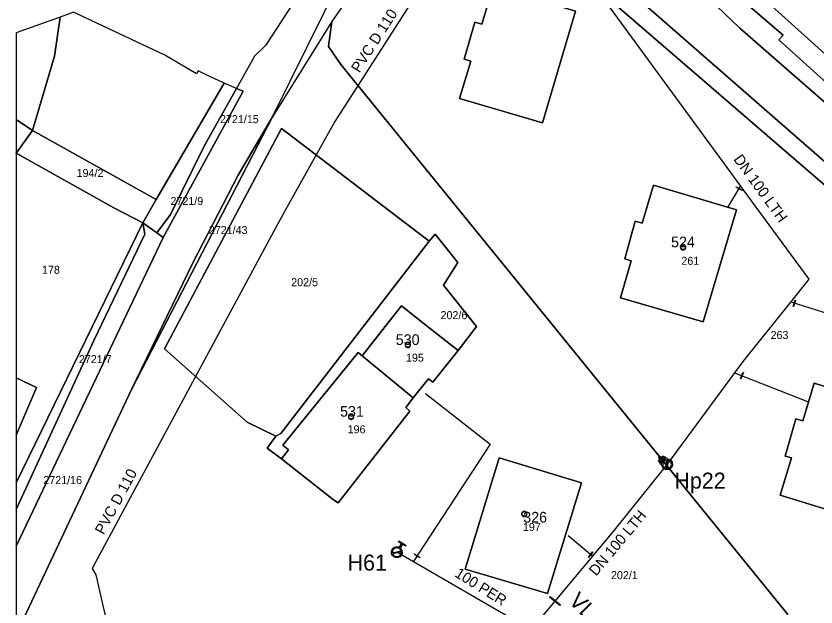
# Model space of a CAD drawing. Extents: x -557590 to -557349, y -1071980 to -1071723.
# Drawn here: x -557590.5 to -557440.5, y -1071889.4 to -1071778.6 of the extents above; entities that cross this region are included whole.
import ezdxf

# ---------------------------------------------------------------- set-up
doc = ezdxf.new("R2010")
doc.units = 0
for name, color, linetype in [('Adresní místo-text', 7, 'Continuous'), ('Armatura - popis', 7, 'Continuous'), ('Armatura vodovodní', 7, 'Continuous'), ('Hydrant', 7, 'Continuous'), ('Označení hydrantu', 7, 'Continuous'), ('Parcela-polygon', 7, 'Continuous'), ('Parcela-text', 7, 'Continuous'), ('Stavební objekt-bod', 7, 'Continuous'), ('Stavební objekt-polygon', 7, 'Continuous'), ('Vodovodní přípojka', 7, 'Continuous'), ('Vodovodní řad', 7, 'Continuous'), ('Řad vodovodní popis', 7, 'Continuous')]:
    doc.layers.add(name, color=color, linetype=linetype)

msp = doc.modelspace()

# ---------------------------------------------------------------- linework, layer by layer
at = {"layer": 'Armatura vodovodní'}
for points in [[(-557455.48, -1071810.64), (-557454.41, -1071811.27), (-557454.45, -1071811.34), (-557455.52, -1071810.7), (-557455.48, -1071810.64)], [(-557444.4, -1071831.89), (-557444.78, -1071833.08), (-557444.85, -1071833.06), (-557444.48, -1071831.86), (-557444.4, -1071831.89)], [(-557454.16, -1071845.46), (-557454.62, -1071846.63), (-557454.69, -1071846.6), (-557454.24, -1071845.43), (-557454.16, -1071845.46)], [(-557515.81, -1071879.44), (-557514.77, -1071880.12), (-557514.81, -1071880.19), (-557515.85, -1071879.5), (-557515.81, -1071879.44)], [(-557482.35, -1071879.11), (-557483.15, -1071880.07), (-557483.21, -1071880.02), (-557482.41, -1071879.06), (-557482.35, -1071879.11)], [(-557490.37, -1071887.39), (-557488.45, -1071888.99), (-557488.55, -1071889.11), (-557490.47, -1071887.51), (-557490.37, -1071887.39)]]:
    msp.add_lwpolyline(points, dxfattribs=at)
at = {"layer": 'Hydrant'}
for points in [[(-557470.05, -1071861.93), (-557469.91, -1071861.79), (-557469.72, -1071861.87)], [(-557469.98, -1071861.31), (-557469.84, -1071861.16)], [(-557469.43, -1071861.95), (-557469.57, -1071862.1), (-557469.8, -1071862.04)], [(-557469.27, -1071861.4), (-557469.36, -1071861.21), (-557469.22, -1071861.07)], [(-557469.25, -1071862), (-557469.12, -1071861.86)], [(-557469.11, -1071861.31), (-557469.04, -1071861.54), (-557469.17, -1071861.68)], [(-557468.73, -1071861.33), (-557468.56, -1071861.44), (-557468.46, -1071861.52)], [(-557468.54, -1071863.43), (-557468.58, -1071861.81)], [(-557468.39, -1071861.81), (-557468.35, -1071863.42)], [(-557469.64, -1071862.58), (-557469.77, -1071862.41)], [(-557469.45, -1071862.78), (-557469.46, -1071862.82)], [(-557518.65, -1071878.22), (-557518.22, -1071877.53), (-557518.8, -1071877.16), (-557518.7, -1071877), (-557517.38, -1071877.83), (-557517.48, -1071877.99), (-557518.06, -1071877.63), (-557518.49, -1071878.32)], [(-557519.91, -1071879.2), (-557518.33, -1071878.84)], [(-557518.29, -1071879.02), (-557519.87, -1071879.39)]]:
    msp.add_lwpolyline(points, dxfattribs=at)
for points, degree in [([(-557469.77, -1071862.41), (-557469.93, -1071862.19), (-557470.05, -1071861.93)], 2), ([(-557469.72, -1071861.87), (-557469.9, -1071861.59), (-557469.98, -1071861.31)], 2), ([(-557469.84, -1071861.16), (-557469.55, -1071861.23), (-557469.27, -1071861.4)], 2), ([(-557469.17, -1071861.68), (-557469.43, -1071861.5), (-557469.73, -1071861.41), (-557469.63, -1071861.71), (-557469.43, -1071861.95)], 3), ([(-557468.35, -1071861.62), (-557468.02, -1071861.66), (-557467.77, -1071861.9), (-557467.47, -1071862.18), (-557467.46, -1071862.6), (-557467.46, -1071863.01), (-557467.74, -1071863.31), (-557468.03, -1071863.61), (-557468.44, -1071863.62), (-557468.85, -1071863.63), (-557469.15, -1071863.34), (-557469.41, -1071863.1), (-557469.45, -1071862.78)], 3), ([(-557468.58, -1071861.81), (-557468.85, -1071861.85), (-557469.06, -1071862.06), (-557469.29, -1071862.3), (-557469.28, -1071862.64), (-557469.27, -1071862.97), (-557469.03, -1071863.21), (-557468.82, -1071863.41), (-557468.54, -1071863.43)], 3), ([(-557469.22, -1071861.07), (-557468.96, -1071861.18), (-557468.73, -1071861.33)], 2), ([(-557469.12, -1071861.86), (-557468.91, -1071861.68), (-557468.64, -1071861.63), (-557468.86, -1071861.45), (-557469.11, -1071861.31)], 3), ([(-557468.46, -1071861.52), (-557468.44, -1071861.54), (-557468.35, -1071861.62)], 2), ([(-557468.35, -1071863.42), (-557468.08, -1071863.39), (-557467.88, -1071863.18), (-557467.65, -1071862.94), (-557467.66, -1071862.6), (-557467.66, -1071862.26), (-557467.91, -1071862.03), (-557468.12, -1071861.83), (-557468.39, -1071861.81)], 3), ([(-557469.8, -1071862.04), (-557469.64, -1071862.28), (-557469.46, -1071862.48)], 2), ([(-557469.46, -1071862.82), (-557469.46, -1071862.8), (-557469.46, -1071862.77), (-557469.57, -1071862.66), (-557469.64, -1071862.58)], 3), ([(-557469.46, -1071862.48), (-557469.43, -1071862.21), (-557469.25, -1071862)], 2), ([(-557518.49, -1071878.32), (-557518.21, -1071878.53), (-557518.13, -1071878.89), (-557518.03, -1071879.29), (-557518.26, -1071879.64), (-557518.47, -1071880), (-557518.88, -1071880.09), (-557519.28, -1071880.18), (-557519.63, -1071879.96), (-557519.98, -1071879.74), (-557520.08, -1071879.34), (-557520.17, -1071878.94), (-557519.95, -1071878.58), (-557519.73, -1071878.23), (-557519.33, -1071878.14), (-557518.97, -1071878.05), (-557518.65, -1071878.22)], 3), ([(-557518.33, -1071878.84), (-557518.43, -1071878.58), (-557518.67, -1071878.42), (-557518.96, -1071878.24), (-557519.29, -1071878.32), (-557519.61, -1071878.39), (-557519.79, -1071878.68), (-557519.95, -1071878.93), (-557519.91, -1071879.2)], 3), ([(-557519.87, -1071879.39), (-557519.78, -1071879.65), (-557519.53, -1071879.8), (-557519.25, -1071879.98), (-557518.92, -1071879.9), (-557518.59, -1071879.83), (-557518.41, -1071879.54), (-557518.26, -1071879.3), (-557518.29, -1071879.02)], 3)]:
    msp.add_open_spline(points, degree=degree, dxfattribs=at)
at = {"layer": 'Parcela-polygon'}
for p, q in [((-557590.46, -1071781.79), (-557590.46, -1071798.04)), ((-557590.46, -1071798.04), (-557590.46, -1071804.35)), ((-557590.46, -1071804.35), (-557590.46, -1071804.36)), ((-557590.46, -1071804.36), (-557590.46, -1071846.45)), ((-557590.46, -1071846.45), (-557590.46, -1071857.16)), ((-557590.46, -1071857.16), (-557590.46, -1071866.09)), ((-557590.46, -1071866.09), (-557590.46, -1071871.1)), ((-557590.46, -1071871.1), (-557590.46, -1071878)), ((-557590.46, -1071878), (-557590.46, -1071894.21))]:
    msp.add_line(p, q, dxfattribs=at)
for points in [[(-557532.39, -1071722.92), (-557523.38, -1071731.14), (-557519.56, -1071737.83), (-557514.49, -1071741.25), (-557511.78, -1071743.08), (-557507.48, -1071745.99), (-557505.88, -1071747.39), (-557407.94, -1071832.97), (-557360.07, -1071868.88), (-557348.7, -1071876.49)], [(-557348.7, -1071872.57), (-557351.33, -1071870.74), (-557377.12, -1071846.76), (-557391.72, -1071835.9), (-557409.36, -1071821.76), (-557431.2, -1071801.51), (-557454.84, -1071780.92), (-557478.14, -1071758.52), (-557494.89, -1071744.04), (-557501.25, -1071740.35), (-557502.97, -1071739.3), (-557506.49, -1071737.04), (-557509.88, -1071734.87), (-557511.32, -1071733.56), (-557512.83, -1071730.19), (-557520.69, -1071722.92)], [(-557491.68, -1071722.92), (-557494.66, -1071727.17), (-557498.21, -1071732.24), (-557371.98, -1071845.92), (-557370.78, -1071844.22), (-557376.44, -1071839.94), (-557374.45, -1071837.16), (-557372.36, -1071834.24), (-557370.27, -1071831.33), (-557368.18, -1071828.42), (-557366.09, -1071825.51), (-557364, -1071822.6), (-557363.05, -1071822.01), (-557359.61, -1071817.07), (-557353.89, -1071820.86), (-557357.44, -1071826.15), (-557355.59, -1071827.4), (-557349.46, -1071818.81), (-557404.92, -1071742.72), (-557414.14, -1071731.67), (-557420.72, -1071725.86), (-557424.8, -1071722.92)], [(-557348.7, -1071864.9), (-557356.49, -1071859.88), (-557361.34, -1071855.51), (-557371.98, -1071845.92), (-557498.21, -1071732.24), (-557498.56, -1071732.08), (-557498.84, -1071732.98), (-557501.22, -1071736.7), (-557499.68, -1071737.96), (-557465.81, -1071765.76), (-557446.72, -1071782.19), (-557447.53, -1071783.1), (-557428.12, -1071800.58), (-557389.66, -1071832.85), (-557377.15, -1071844.11), (-557348.7, -1071869.27)], [(-557348.7, -1071869.27), (-557377.15, -1071844.11), (-557389.66, -1071832.85), (-557428.12, -1071800.58), (-557447.53, -1071783.1), (-557446.72, -1071782.19), (-557465.81, -1071765.76), (-557499.68, -1071737.96), (-557501.22, -1071736.7), (-557503.91, -1071734.49), (-557506.49, -1071737.04), (-557502.97, -1071739.3), (-557501.25, -1071740.35), (-557494.89, -1071744.04), (-557478.14, -1071758.52), (-557454.84, -1071780.92), (-557431.2, -1071801.51), (-557409.36, -1071821.76), (-557391.72, -1071835.9), (-557377.12, -1071846.76), (-557351.33, -1071870.74), (-557348.7, -1071872.57)], [(-557590.46, -1071894.21), (-557589.01, -1071891.45), (-557568.8, -1071848.59), (-557557.24, -1071824.77), (-557548.84, -1071808.44), (-557542.42, -1071797.49), (-557529.5, -1071771.47), (-557511.78, -1071743.08), (-557514.49, -1071741.25), (-557521.38, -1071750.42), (-557524.29, -1071754.35), (-557543.7, -1071784.14), (-557545.78, -1071786.13), (-557549.16, -1071792.19), (-557547.9, -1071792.73), (-557562.91, -1071820.1), (-557590.46, -1071878)], [(-557348.7, -1071876.49), (-557360.07, -1071868.88), (-557407.94, -1071832.97), (-557505.88, -1071747.39), (-557507.48, -1071745.99), (-557509.91, -1071749.02), (-557508.17, -1071750.52), (-557408.88, -1071836.21), (-557387.5, -1071856.25), (-557385.01, -1071858.11), (-557382.34, -1071860.11), (-557379.67, -1071862.11), (-557376.99, -1071864.11), (-557374.36, -1071866.09), (-557371.65, -1071868.11), (-557368.98, -1071870.11), (-557366.31, -1071872.11), (-557363.63, -1071874.12), (-557360.97, -1071876.11), (-557358.29, -1071878.11), (-557356.55, -1071879.44), (-557348.7, -1071885.41)], [(-557408.88, -1071836.21), (-557508.17, -1071750.52), (-557509.91, -1071749.02), (-557531.29, -1071779.68), (-557531.92, -1071784.31), (-557529.61, -1071787.72), (-557445.83, -1071890.76)], [(-557590.46, -1071798.04), (-557587.38, -1071800.05), (-557583.28, -1071786.13), (-557582.18, -1071778.84), (-557590.46, -1071781.79)], [(-557445.83, -1071890.76), (-557529.61, -1071787.72), (-557531.92, -1071784.31), (-557531.29, -1071779.68), (-557542.42, -1071797.49), (-557568.8, -1071848.59), (-557589.01, -1071891.45)], [(-557590.46, -1071804.35), (-557590.46, -1071804.35), (-557587.38, -1071800.05), (-557590.46, -1071798.04)], [(-557513.02, -1071820.8), (-557511.94, -1071819.53), (-557507.66, -1071824.81), (-557510.33, -1071829.09), (-557504.14, -1071836.78), (-557507.6, -1071841.29), (-557512.38, -1071847.24), (-557513.19, -1071846.59), (-557515.28, -1071849.25), (-557516.01, -1071850.19), (-557517.41, -1071851.98), (-557516.66, -1071852.7), (-557530.08, -1071869.85), (-557530.96, -1071869.3), (-557540.72, -1071861.63), (-557543.37, -1071859.63), (-557541.76, -1071857.33), (-557547.13, -1071854.74), (-557562.62, -1071841.01), (-557540.68, -1071799.68), (-557513.02, -1071820.8)], [(-557590.46, -1071866.09), (-557566.69, -1071817.37), (-557572.16, -1071814.55), (-557590.46, -1071804.35), (-557590.46, -1071804.36)], [(-557590.46, -1071804.36), (-557590.46, -1071804.35), (-557590.46, -1071804.35)], [(-557590.46, -1071871.1), (-557575.79, -1071839.29), (-557566.34, -1071819.48), (-557566.69, -1071817.37), (-557590.46, -1071866.09)], [(-557590.46, -1071878), (-557562.91, -1071820.1), (-557564.05, -1071819.28), (-557566.69, -1071817.37), (-557566.34, -1071819.48), (-557575.79, -1071839.29), (-557590.46, -1071871.1)], [(-557590.46, -1071857.16), (-557587.87, -1071851.19), (-557586.6, -1071848.25), (-557590.46, -1071846.45)], [(-557590.46, -1071846.45), (-557586.6, -1071848.25), (-557587.87, -1071851.19), (-557590.46, -1071857.16)], [(-557431.85, -1071873.19), (-557447.24, -1071868.43), (-557445.12, -1071861.45), (-557446.3, -1071861.09), (-557444.31, -1071854.11), (-557443.01, -1071854.5), (-557440.87, -1071847.45), (-557430.15, -1071850.71)], [(-557484.5, -1071866.11), (-557490.88, -1071886.85), (-557506.29, -1071882.29), (-557499.92, -1071861.43), (-557484.5, -1071866.11)]]:
    msp.add_lwpolyline(points, dxfattribs=at)
for points in [[(-557491.82, -1071798.65), (-557507.35, -1071794.09), (-557505.25, -1071787.08), (-557506.51, -1071786.71), (-557504.5, -1071779.75), (-557503.17, -1071780.15), (-557501.03, -1071773.01), (-557485.62, -1071777.72)], [(-557501.03, -1071773.01), (-557503.17, -1071780.15), (-557504.5, -1071779.75), (-557506.51, -1071786.71), (-557505.25, -1071787.08), (-557507.35, -1071794.09), (-557491.82, -1071798.65), (-557485.62, -1071777.72)], [(-557551.46, -1071791.21), (-557555.08, -1071789.5), (-557556.32, -1071788.92), (-557556.65, -1071789.47), (-557562.59, -1071785.96), (-557579.67, -1071777.91), (-557582.18, -1071778.84), (-557583.28, -1071786.13), (-557587.38, -1071800.05), (-557564.18, -1071813.04)], [(-557549.16, -1071792.19), (-557551.46, -1071791.21), (-557564.18, -1071813.04), (-557566.69, -1071817.37), (-557564.05, -1071819.28), (-557561.52, -1071815.85), (-557555.11, -1071802.86)], [(-557562.91, -1071820.1), (-557547.9, -1071792.73), (-557549.16, -1071792.19), (-557555.11, -1071802.86), (-557561.52, -1071815.85), (-557564.05, -1071819.28)], [(-557568.8, -1071848.59), (-557542.42, -1071797.49), (-557548.84, -1071808.44), (-557557.24, -1071824.77)], [(-557590.46, -1071804.35), (-557572.16, -1071814.55), (-557566.69, -1071817.37), (-557564.18, -1071813.04), (-557587.38, -1071800.05)], [(-557513.02, -1071820.8), (-557540.68, -1071799.68), (-557562.62, -1071841.01), (-557547.13, -1071854.74), (-557541.76, -1071857.33), (-557540.82, -1071856.86)], [(-557474.43, -1071817.09), (-557476.38, -1071824.15), (-557475.17, -1071824.5), (-557477.18, -1071831.41), (-557461.72, -1071835.91), (-557455.47, -1071814.94), (-557471.03, -1071810.33), (-557473.12, -1071817.47)], [(-557475.17, -1071824.5), (-557476.38, -1071824.15), (-557474.43, -1071817.09), (-557473.12, -1071817.47), (-557471.03, -1071810.33), (-557455.47, -1071814.94), (-557461.72, -1071835.91), (-557477.18, -1071831.41)], [(-557511.94, -1071819.53), (-557513.02, -1071820.8), (-557540.82, -1071856.86), (-557541.76, -1071857.33), (-557543.37, -1071859.63), (-557540.72, -1071861.63), (-557539.37, -1071859.91), (-557540.45, -1071859.06), (-557526.36, -1071841.71), (-557525.57, -1071842.32), (-557520.58, -1071835.96), (-557518.23, -1071832.96), (-557513.35, -1071836.79), (-557508.5, -1071840.59), (-557507.6, -1071841.29), (-557504.14, -1071836.78), (-557510.33, -1071829.09), (-557507.66, -1071824.81)], [(-557520.58, -1071835.96), (-557525.57, -1071842.32), (-557516.01, -1071850.19), (-557515.28, -1071849.25), (-557513.19, -1071846.59), (-557512.38, -1071847.24), (-557507.6, -1071841.29), (-557508.5, -1071840.59), (-557513.35, -1071836.79), (-557518.23, -1071832.96)], [(-557525.57, -1071842.32), (-557526.36, -1071841.71), (-557540.45, -1071859.06), (-557539.37, -1071859.91), (-557540.72, -1071861.63), (-557530.96, -1071869.3), (-557530.08, -1071869.85), (-557516.66, -1071852.7), (-557517.41, -1071851.98), (-557516.01, -1071850.19)], [(-557425.5, -1071852.13), (-557430.15, -1071850.71), (-557440.87, -1071847.45), (-557443.01, -1071854.5), (-557444.31, -1071854.11), (-557446.3, -1071861.09), (-557445.12, -1071861.45), (-557447.24, -1071868.43), (-557431.85, -1071873.19)], [(-557499.92, -1071861.43), (-557506.29, -1071882.29), (-557490.88, -1071886.85), (-557484.5, -1071866.11)]]:
    msp.add_lwpolyline(points, close=True, dxfattribs=at)
at = {"layer": 'Stavební objekt-bod'}
for points in [[(-557465.45, -1071821.47), (-557465.32, -1071821.47), (-557465.2, -1071821.53), (-557465.09, -1071821.6), (-557465.02, -1071821.72), (-557464.95, -1071821.84), (-557464.95, -1071821.97), (-557464.95, -1071822.1), (-557465.02, -1071822.22), (-557465.08, -1071822.34), (-557465.2, -1071822.4), (-557465.32, -1071822.47), (-557465.45, -1071822.47), (-557465.58, -1071822.47), (-557465.7, -1071822.4), (-557465.82, -1071822.34), (-557465.88, -1071822.22), (-557465.95, -1071822.1), (-557465.95, -1071821.97), (-557465.95, -1071821.84), (-557465.88, -1071821.72), (-557465.82, -1071821.6), (-557465.7, -1071821.53), (-557465.58, -1071821.47), (-557465.45, -1071821.47)], [(-557465.89, -1071821.97), (-557465.89, -1071822.08), (-557465.83, -1071822.19), (-557465.77, -1071822.29), (-557465.67, -1071822.35), (-557465.56, -1071822.41), (-557465.45, -1071822.41), (-557465.34, -1071822.41), (-557465.23, -1071822.35), (-557465.13, -1071822.29), (-557465.07, -1071822.19), (-557465.01, -1071822.08), (-557465.01, -1071821.97), (-557465.01, -1071821.86), (-557465.07, -1071821.75), (-557465.13, -1071821.65), (-557465.24, -1071821.59), (-557465.34, -1071821.53), (-557465.45, -1071821.53), (-557465.56, -1071821.53), (-557465.67, -1071821.59), (-557465.77, -1071821.65), (-557465.83, -1071821.75), (-557465.89, -1071821.86), (-557465.89, -1071821.97)], [(-557517.04, -1071839.77), (-557516.91, -1071839.77), (-557516.79, -1071839.83), (-557516.68, -1071839.9), (-557516.61, -1071840.02), (-557516.54, -1071840.14), (-557516.54, -1071840.27), (-557516.54, -1071840.4), (-557516.61, -1071840.52), (-557516.67, -1071840.64), (-557516.79, -1071840.7), (-557516.91, -1071840.77), (-557517.04, -1071840.77), (-557517.17, -1071840.77), (-557517.29, -1071840.7), (-557517.41, -1071840.64), (-557517.47, -1071840.52), (-557517.54, -1071840.4), (-557517.54, -1071840.27), (-557517.54, -1071840.14), (-557517.47, -1071840.02), (-557517.41, -1071839.9), (-557517.29, -1071839.83), (-557517.17, -1071839.77), (-557517.04, -1071839.77)], [(-557517.48, -1071840.27), (-557517.48, -1071840.38), (-557517.42, -1071840.49), (-557517.36, -1071840.59), (-557517.26, -1071840.65), (-557517.15, -1071840.71), (-557517.04, -1071840.71), (-557516.93, -1071840.71), (-557516.82, -1071840.65), (-557516.72, -1071840.59), (-557516.66, -1071840.49), (-557516.6, -1071840.38), (-557516.6, -1071840.27), (-557516.6, -1071840.16), (-557516.66, -1071840.05), (-557516.72, -1071839.95), (-557516.83, -1071839.89), (-557516.93, -1071839.83), (-557517.04, -1071839.83), (-557517.15, -1071839.83), (-557517.26, -1071839.89), (-557517.36, -1071839.95), (-557517.42, -1071840.05), (-557517.48, -1071840.16), (-557517.48, -1071840.27)], [(-557527.67, -1071853.21), (-557527.54, -1071853.21), (-557527.42, -1071853.27), (-557527.31, -1071853.34), (-557527.24, -1071853.46), (-557527.17, -1071853.58), (-557527.17, -1071853.71), (-557527.17, -1071853.84), (-557527.24, -1071853.96), (-557527.3, -1071854.08), (-557527.42, -1071854.14), (-557527.54, -1071854.21), (-557527.67, -1071854.21), (-557527.8, -1071854.21), (-557527.92, -1071854.14), (-557528.04, -1071854.08), (-557528.1, -1071853.96), (-557528.17, -1071853.84), (-557528.17, -1071853.71), (-557528.17, -1071853.58), (-557528.1, -1071853.46), (-557528.04, -1071853.34), (-557527.92, -1071853.27), (-557527.8, -1071853.21), (-557527.67, -1071853.21)], [(-557528.11, -1071853.71), (-557528.11, -1071853.82), (-557528.05, -1071853.93), (-557527.99, -1071854.03), (-557527.89, -1071854.09), (-557527.78, -1071854.15), (-557527.67, -1071854.15), (-557527.56, -1071854.15), (-557527.45, -1071854.09), (-557527.35, -1071854.03), (-557527.29, -1071853.93), (-557527.23, -1071853.82), (-557527.23, -1071853.71), (-557527.23, -1071853.6), (-557527.29, -1071853.49), (-557527.35, -1071853.39), (-557527.46, -1071853.33), (-557527.56, -1071853.27), (-557527.67, -1071853.27), (-557527.78, -1071853.27), (-557527.89, -1071853.33), (-557527.99, -1071853.39), (-557528.05, -1071853.49), (-557528.11, -1071853.6), (-557528.11, -1071853.71)], [(-557495.21, -1071871.44), (-557495.08, -1071871.44), (-557494.96, -1071871.5), (-557494.85, -1071871.57), (-557494.78, -1071871.69), (-557494.71, -1071871.81), (-557494.71, -1071871.94), (-557494.71, -1071872.07), (-557494.78, -1071872.19), (-557494.84, -1071872.31), (-557494.96, -1071872.37), (-557495.08, -1071872.44), (-557495.21, -1071872.44), (-557495.34, -1071872.44), (-557495.46, -1071872.37), (-557495.58, -1071872.31), (-557495.64, -1071872.19), (-557495.71, -1071872.07), (-557495.71, -1071871.94), (-557495.71, -1071871.81), (-557495.64, -1071871.69), (-557495.58, -1071871.57), (-557495.46, -1071871.5), (-557495.34, -1071871.44), (-557495.21, -1071871.44)], [(-557495.65, -1071871.94), (-557495.65, -1071872.05), (-557495.59, -1071872.16), (-557495.53, -1071872.26), (-557495.43, -1071872.32), (-557495.32, -1071872.38), (-557495.21, -1071872.38), (-557495.1, -1071872.38), (-557494.99, -1071872.32), (-557494.89, -1071872.26), (-557494.83, -1071872.16), (-557494.77, -1071872.05), (-557494.77, -1071871.94), (-557494.77, -1071871.83), (-557494.83, -1071871.72), (-557494.89, -1071871.62), (-557495, -1071871.56), (-557495.1, -1071871.5), (-557495.21, -1071871.5), (-557495.32, -1071871.5), (-557495.43, -1071871.56), (-557495.53, -1071871.62), (-557495.59, -1071871.72), (-557495.65, -1071871.83), (-557495.65, -1071871.94)]]:
    msp.add_open_spline(points, degree=3, dxfattribs=at)
at = {"layer": 'Stavební objekt-polygon'}
msp.add_line((-557590.46, -1071846.45), (-557590.46, -1071857.16), dxfattribs=at)
for points in [[(-557501.03, -1071773.01), (-557503.17, -1071780.15), (-557504.5, -1071779.75), (-557506.51, -1071786.71), (-557505.25, -1071787.08), (-557507.35, -1071794.09), (-557491.82, -1071798.65), (-557485.62, -1071777.72)], [(-557455.47, -1071814.94), (-557471.03, -1071810.33), (-557473.12, -1071817.47), (-557474.43, -1071817.09), (-557476.38, -1071824.15), (-557475.17, -1071824.5), (-557477.18, -1071831.41), (-557461.72, -1071835.91)], [(-557520.58, -1071835.96), (-557525.57, -1071842.32), (-557516.01, -1071850.19), (-557515.28, -1071849.25), (-557513.19, -1071846.59), (-557512.38, -1071847.24), (-557507.6, -1071841.29), (-557508.5, -1071840.59), (-557513.35, -1071836.79), (-557518.23, -1071832.96)], [(-557516.66, -1071852.7), (-557517.41, -1071851.98), (-557516.01, -1071850.19), (-557525.57, -1071842.32), (-557526.36, -1071841.71), (-557540.45, -1071859.06), (-557539.37, -1071859.91), (-557540.72, -1071861.63), (-557530.96, -1071869.3), (-557530.08, -1071869.85)], [(-557425.5, -1071852.13), (-557430.15, -1071850.71), (-557440.87, -1071847.45), (-557443.01, -1071854.5), (-557444.31, -1071854.11), (-557446.3, -1071861.09), (-557445.12, -1071861.45), (-557447.24, -1071868.43), (-557431.85, -1071873.19)], [(-557506.29, -1071882.29), (-557490.88, -1071886.85), (-557484.5, -1071866.11), (-557499.92, -1071861.43)]]:
    msp.add_lwpolyline(points, close=True, dxfattribs=at)
msp.add_lwpolyline([(-557590.46, -1071857.16), (-557587.87, -1071851.19), (-557586.6, -1071848.25), (-557590.46, -1071846.45)], dxfattribs=at)
at = {"layer": 'Vodovodní přípojka'}
for p, q in [((-557457.04, -1071814.48), (-557454.7, -1071810.54)), ((-557455.82, -1071845.49), (-557442.15, -1071850.84)), ((-557482.44, -1071879.86), (-557487, -1071876.04))]:
    msp.add_line(p, q, dxfattribs=at)
for points in [[(-557426.24, -1071838.24), (-557445.22, -1071832.28), (-557445.33, -1071832.25)], [(-557513.75, -1071849.38), (-557501.63, -1071858.87), (-557516.02, -1071880.9)]]:
    msp.add_lwpolyline(points, dxfattribs=at)
at = {"layer": 'Vodovodní řad'}
msp.add_line((-557541.72, -1071818.13), (-557575.7, -1071881.23), dxfattribs=at)
for points in [[(-557496.75, -1071758.67), (-557512.36, -1071769.71), (-557530.72, -1071798.39), (-557538.44, -1071812.23)], [(-557496.34, -1071759.05), (-557483.57, -1071771.03), (-557454.7, -1071810.54), (-557454.27, -1071811.12), (-557441.87, -1071827.93), (-557445.33, -1071832.25), (-557454.27, -1071843.38), (-557455.82, -1071845.49), (-557468.46, -1071862.62)], [(-557538.44, -1071812.23), (-557538.47, -1071812.28), (-557539.31, -1071813.84), (-557541.71, -1071818.11), (-557541.72, -1071818.13)], [(-557468.47, -1071862.62), (-557478.61, -1071875.28), (-557489.46, -1071888.25)], [(-557489.46, -1071888.25), (-557490.76, -1071889.8), (-557493.98, -1071893.66), (-557519.1, -1071879.11)], [(-557575.7, -1071881.23), (-557576.18, -1071882.13), (-557575.53, -1071883.32)], [(-557575.53, -1071883.32), (-557570.55, -1071904.9), (-557575.62, -1071911.53), (-557578.43, -1071915.2), (-557589.25, -1071929.32), (-557590.46, -1071931.04)]]:
    msp.add_lwpolyline(points, dxfattribs=at)

# ---------------------------------------------------------------- texts
at = {"layer": 'Adresní místo-text'}
for s, p in [('524', (-557467.71, -1071821.97)), ('530', (-557519.3, -1071840.27)), ('531', (-557529.74, -1071853.71)), ('326', (-557495.41, -1071873.55))]:
    msp.add_text(s, height=2, dxfattribs=at).set_placement(p)
at = {"layer": 'Armatura - popis'}
msp.add_text('VL-52', height=3, rotation=315, dxfattribs=at).set_placement((-557487.03, -1071888.45))
at = {"layer": 'Označení hydrantu'}
for s, p in [('Hp22', (-557467.08, -1071867.19)), ('H61', (-557528.32, -1071882.55))]:
    msp.add_text(s, height=3, dxfattribs=at).set_placement(p)
at = {"layer": 'Parcela-text'}
for s, p in [('2721/15', (-557552.23, -1071798.7)), ('194/2', (-557579.1, -1071808.8)), ('2721/9', (-557561.51, -1071814.04)), ('2721/43', (-557554.33, -1071819.49)), ('261', (-557465.78, -1071825.25)), ('178', (-557585.59, -1071826.93)), ('202/5', (-557538.89, -1071829.26)), ('202/6', (-557510.9, -1071835.43)), ('263', (-557449.06, -1071839.15)), ('2721/7', (-557578.68, -1071843.68)), ('195', (-557517.38, -1071843.4)), ('196', (-557528.32, -1071856.83)), ('2721/16', (-557585.34, -1071866.34)), ('197', (-557495.47, -1071875.12)), ('202/1', (-557478.97, -1071884.15))]:
    msp.add_text(s, height=1.5, dxfattribs=at).set_placement(p)
at = {"layer": 'Řad vodovodní popis'}
for s, rotation, p in [('PVC D 110', 57.3745, (-557526.11, -1071789.41)), ('DN 100 LTH', 305.9686, (-557456.09, -1071805.48)), ('PVC D 110', 61.7005, (-557574.04, -1071875.96)), ('DN 100 LTH', 50.0897, (-557481.74, -1071883.69)), (' 100 PER', 327.9946, (-557509.04, -1071883.16))]:
    msp.add_text(s, height=2, rotation=rotation, dxfattribs=at).set_placement(p)

doc.saveas('drawing.dxf')
